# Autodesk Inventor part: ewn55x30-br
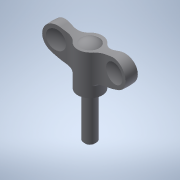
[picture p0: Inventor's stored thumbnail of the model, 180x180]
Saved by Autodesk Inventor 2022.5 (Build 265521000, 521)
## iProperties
Created: 2016-12
Part Number: ewn55x30-br
Material: 一般
Document SubType Name: Modeling
Designer: imaocorp
Density: 1 g/cm^3
Appearance: 既定
Author: imaocorp
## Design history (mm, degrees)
node "ewn55x30-br.x_t1"
node "ewn55x30-br"
node "Base1"
